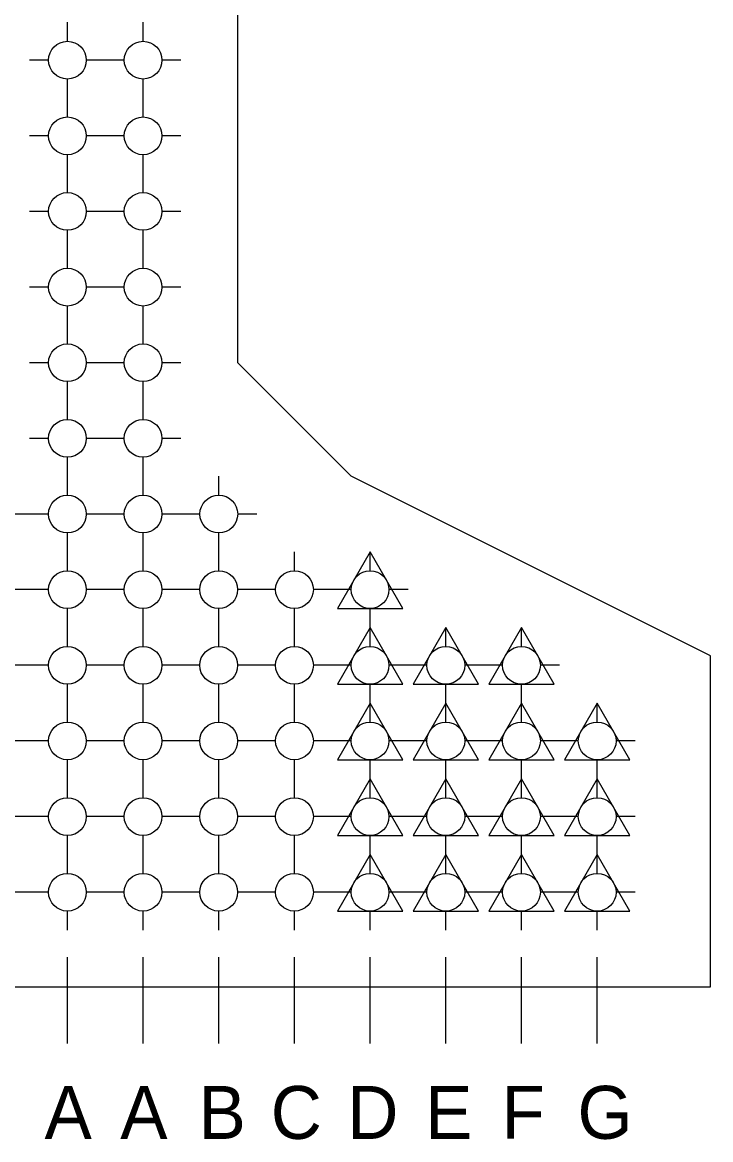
# Model space of a CAD drawing. Extents: x 998.6 to 1033.3, y 1000 to 1011.
# Drawn here: x 1010.397 to 1011.155, y 1001.342 to 1002.573 of the extents above; entities that cross this region are included whole.
import ezdxf

# ---------------------------------------------------------------- set-up
doc = ezdxf.new("R2010")
doc.units = 0
doc.layers.add('Working Level 1', color=7, linetype='Continuous')

msp = doc.modelspace()

# ---------------------------------------------------------------- linework, layer by layer
at = {"layer": 'Working Level 1'}
for p, q in [((1010.6339, 1002.1977), (1010.6339, 1004.0935)), ((1010.4465, 1002.552), (1010.4465, 1002.5729)), ((1010.5298, 1002.552), (1010.5298, 1002.5729)), ((1010.4256, 1002.5312), (1010.4048, 1002.5312)), ((1010.4881, 1002.5312), (1010.4673, 1002.5312)), ((1010.5089, 1002.5312), (1010.4881, 1002.5312)), ((1010.5714, 1002.5312), (1010.5506, 1002.5312)), ((1010.4464, 1002.4895), (1010.4464, 1002.5104)), ((1010.5297, 1002.4895), (1010.5297, 1002.5104)), ((1010.4465, 1002.4687), (1010.4465, 1002.4895)), ((1010.5298, 1002.4687), (1010.5298, 1002.4895)), ((1010.4256, 1002.4478), (1010.4048, 1002.4478)), ((1010.4881, 1002.4478), (1010.4673, 1002.4478)), ((1010.5089, 1002.4478), (1010.4881, 1002.4478)), ((1010.5714, 1002.4478), (1010.5506, 1002.4478)), ((1010.4464, 1002.4062), (1010.4464, 1002.427)), ((1010.5297, 1002.4062), (1010.5297, 1002.427)), ((1010.4465, 1002.3853), (1010.4465, 1002.4062)), ((1010.5298, 1002.3853), (1010.5298, 1002.4062)), ((1010.4256, 1002.3645), (1010.4048, 1002.3645)), ((1010.4881, 1002.3645), (1010.4673, 1002.3645)), ((1010.5089, 1002.3645), (1010.4881, 1002.3645)), ((1010.5714, 1002.3645), (1010.5506, 1002.3645)), ((1010.4464, 1002.3228), (1010.4464, 1002.3437)), ((1010.5297, 1002.3228), (1010.5297, 1002.3437)), ((1010.4465, 1002.302), (1010.4465, 1002.3228)), ((1010.5298, 1002.302), (1010.5298, 1002.3228)), ((1010.4256, 1002.2811), (1010.4048, 1002.2811)), ((1010.4881, 1002.2811), (1010.4673, 1002.2811)), ((1010.5089, 1002.2811), (1010.4881, 1002.2811)), ((1010.5714, 1002.2811), (1010.5506, 1002.2811)), ((1010.4464, 1002.2395), (1010.4464, 1002.2603)), ((1010.5297, 1002.2395), (1010.5297, 1002.2603)), ((1010.4464, 1002.2186), (1010.4464, 1002.2395)), ((1010.5297, 1002.2186), (1010.5297, 1002.2395)), ((1010.4256, 1002.1978), (1010.4047, 1002.1978)), ((1010.4881, 1002.1978), (1010.4672, 1002.1978)), ((1010.5089, 1002.1978), (1010.488, 1002.1978)), ((1010.5714, 1002.1978), (1010.5505, 1002.1978)), ((1010.7589, 1002.0727), (1010.6339, 1002.1977)), ((1010.4464, 1002.1561), (1010.4464, 1002.177)), ((1010.5297, 1002.1561), (1010.5297, 1002.177)), ((1010.4464, 1002.1353), (1010.4464, 1002.1561)), ((1010.5297, 1002.1353), (1010.5297, 1002.1561)), ((1010.4256, 1002.1145), (1010.4047, 1002.1145)), ((1010.4881, 1002.1145), (1010.4672, 1002.1145)), ((1010.5089, 1002.1145), (1010.488, 1002.1145)), ((1010.5714, 1002.1145), (1010.5505, 1002.1145)), ((1010.4464, 1002.0728), (1010.4464, 1002.0936)), ((1010.5297, 1002.0728), (1010.5297, 1002.0936)), ((1010.4464, 1002.0519), (1010.4464, 1002.0728)), ((1010.5297, 1002.0519), (1010.5297, 1002.0728)), ((1010.6131, 1002.0519), (1010.6131, 1002.0728)), ((1011.1547, 1001.8748), (1010.7589, 1002.0727)), ((1010.4048, 1002.0311), (1010.3839, 1002.0311)), ((1010.4256, 1002.0311), (1010.4047, 1002.0311)), ((1010.4881, 1002.0311), (1010.4672, 1002.0311)), ((1010.5089, 1002.0311), (1010.488, 1002.0311)), ((1010.5714, 1002.0311), (1010.5505, 1002.0311)), ((1010.5923, 1002.0311), (1010.5714, 1002.0311)), ((1010.6548, 1002.0311), (1010.6339, 1002.0311)), ((1010.4464, 1001.9894), (1010.4464, 1002.0103)), ((1010.5297, 1001.9894), (1010.5297, 1002.0103)), ((1010.6131, 1001.9894), (1010.6131, 1002.0103)), ((1010.4464, 1001.9686), (1010.4464, 1001.9894)), ((1010.5297, 1001.9686), (1010.5297, 1001.9894)), ((1010.6131, 1001.9686), (1010.6131, 1001.9894)), ((1010.6964, 1001.9686), (1010.6964, 1001.9894)), ((1010.7798, 1001.9894), (1010.7437, 1001.9269)), ((1010.7798, 1001.9686), (1010.7798, 1001.9894)), ((1010.8158, 1001.9269), (1010.7798, 1001.9894)), ((1010.4048, 1001.9478), (1010.3839, 1001.9478)), ((1010.4256, 1001.9478), (1010.4047, 1001.9478)), ((1010.4881, 1001.9478), (1010.4672, 1001.9478)), ((1010.5089, 1001.9478), (1010.488, 1001.9478)), ((1010.5714, 1001.9478), (1010.5505, 1001.9478)), ((1010.5922, 1001.9478), (1010.5714, 1001.9478)), ((1010.6548, 1001.9478), (1010.6339, 1001.9478)), ((1010.6756, 1001.9478), (1010.6547, 1001.9478)), ((1010.7381, 1001.9478), (1010.7172, 1001.9478)), ((1010.7589, 1001.9478), (1010.7381, 1001.9478)), ((1010.8215, 1001.9478), (1010.8006, 1001.9478)), ((1010.4464, 1001.9061), (1010.4464, 1001.9269)), ((1010.5297, 1001.9061), (1010.5297, 1001.9269)), ((1010.613, 1001.9061), (1010.613, 1001.9269)), ((1010.6964, 1001.9061), (1010.6964, 1001.9269)), ((1010.7437, 1001.9269), (1010.8158, 1001.9269)), ((1010.7797, 1001.9061), (1010.7797, 1001.9269)), ((1010.4464, 1001.8852), (1010.4464, 1001.9061)), ((1010.5297, 1001.8852), (1010.5297, 1001.9061)), ((1010.6131, 1001.8852), (1010.6131, 1001.9061)), ((1010.6964, 1001.8852), (1010.6964, 1001.9061)), ((1010.7798, 1001.9061), (1010.7437, 1001.8436)), ((1010.7798, 1001.8852), (1010.7798, 1001.9061)), ((1010.8158, 1001.8436), (1010.7798, 1001.9061)), ((1010.8631, 1001.9061), (1010.827, 1001.8436)), ((1010.8631, 1001.8852), (1010.8631, 1001.9061)), ((1010.8992, 1001.8436), (1010.8631, 1001.9061)), ((1010.9465, 1001.9061), (1010.9104, 1001.8436)), ((1010.9465, 1001.8852), (1010.9465, 1001.9061)), ((1010.9825, 1001.8436), (1010.9465, 1001.9061)), ((1011.1547, 1001.5102), (1011.1547, 1001.8748)), ((1010.4048, 1001.8644), (1010.3839, 1001.8644)), ((1010.4256, 1001.8644), (1010.4047, 1001.8644)), ((1010.4881, 1001.8644), (1010.4672, 1001.8644)), ((1010.5089, 1001.8644), (1010.488, 1001.8644)), ((1010.5714, 1001.8644), (1010.5505, 1001.8644)), ((1010.5922, 1001.8644), (1010.5714, 1001.8644)), ((1010.6548, 1001.8644), (1010.6339, 1001.8644)), ((1010.6756, 1001.8644), (1010.6547, 1001.8644)), ((1010.7381, 1001.8644), (1010.7172, 1001.8644)), ((1010.7589, 1001.8644), (1010.7381, 1001.8644)), ((1010.8215, 1001.8644), (1010.8006, 1001.8644)), ((1010.8423, 1001.8644), (1010.8214, 1001.8644)), ((1010.9048, 1001.8644), (1010.8839, 1001.8644)), ((1010.9256, 1001.8644), (1010.9048, 1001.8644)), ((1010.9882, 1001.8644), (1010.9673, 1001.8644)), ((1010.4464, 1001.8227), (1010.4464, 1001.8436)), ((1010.5297, 1001.8227), (1010.5297, 1001.8436)), ((1010.613, 1001.8227), (1010.613, 1001.8436)), ((1010.6964, 1001.8227), (1010.6964, 1001.8436)), ((1010.7437, 1001.8436), (1010.8158, 1001.8436)), ((1010.7797, 1001.8227), (1010.7797, 1001.8436)), ((1010.827, 1001.8436), (1010.8992, 1001.8436)), ((1010.8631, 1001.8227), (1010.8631, 1001.8436)), ((1010.9104, 1001.8436), (1010.9825, 1001.8436)), ((1010.9464, 1001.8227), (1010.9464, 1001.8436)), ((1010.4464, 1001.8019), (1010.4464, 1001.8227)), ((1010.5297, 1001.8019), (1010.5297, 1001.8227)), ((1010.6131, 1001.8019), (1010.6131, 1001.8227)), ((1010.6964, 1001.8019), (1010.6964, 1001.8227)), ((1010.7798, 1001.8227), (1010.7437, 1001.7602)), ((1010.7798, 1001.8019), (1010.7798, 1001.8227)), ((1010.8158, 1001.7602), (1010.7798, 1001.8227)), ((1010.8631, 1001.8227), (1010.827, 1001.7602)), ((1010.8631, 1001.8019), (1010.8631, 1001.8227)), ((1010.8992, 1001.7602), (1010.8631, 1001.8227)), ((1010.9465, 1001.8227), (1010.9104, 1001.7602)), ((1010.9465, 1001.8019), (1010.9465, 1001.8227)), ((1010.9825, 1001.7602), (1010.9465, 1001.8227)), ((1011.0298, 1001.8227), (1010.9937, 1001.7602)), ((1011.0298, 1001.8019), (1011.0298, 1001.8227)), ((1011.0659, 1001.7602), (1011.0298, 1001.8227)), ((1010.4048, 1001.7811), (1010.3839, 1001.7811)), ((1010.4256, 1001.7811), (1010.4047, 1001.7811)), ((1010.4881, 1001.7811), (1010.4672, 1001.7811)), ((1010.5089, 1001.7811), (1010.488, 1001.7811)), ((1010.5714, 1001.7811), (1010.5505, 1001.7811)), ((1010.5922, 1001.7811), (1010.5714, 1001.7811)), ((1010.6548, 1001.7811), (1010.6339, 1001.7811)), ((1010.6756, 1001.7811), (1010.6547, 1001.7811)), ((1010.7381, 1001.7811), (1010.7172, 1001.7811)), ((1010.7589, 1001.7811), (1010.7381, 1001.7811)), ((1010.8215, 1001.7811), (1010.8006, 1001.7811)), ((1010.8423, 1001.7811), (1010.8214, 1001.7811)), ((1010.9048, 1001.7811), (1010.8839, 1001.7811)), ((1010.9256, 1001.7811), (1010.9048, 1001.7811)), ((1010.9882, 1001.7811), (1010.9673, 1001.7811)), ((1011.009, 1001.7811), (1010.9881, 1001.7811)), ((1011.0715, 1001.7811), (1011.0506, 1001.7811)), ((1010.4464, 1001.7394), (1010.4464, 1001.7602)), ((1010.5297, 1001.7394), (1010.5297, 1001.7602)), ((1010.613, 1001.7394), (1010.613, 1001.7602)), ((1010.6964, 1001.7394), (1010.6964, 1001.7602)), ((1010.7437, 1001.7602), (1010.8158, 1001.7602)), ((1010.7797, 1001.7394), (1010.7797, 1001.7602)), ((1010.827, 1001.7602), (1010.8992, 1001.7602)), ((1010.8631, 1001.7394), (1010.8631, 1001.7602)), ((1010.9104, 1001.7602), (1010.9825, 1001.7602)), ((1010.9464, 1001.7394), (1010.9464, 1001.7602)), ((1010.9937, 1001.7602), (1011.0659, 1001.7602)), ((1011.0298, 1001.7394), (1011.0298, 1001.7602)), ((1010.4464, 1001.7185), (1010.4464, 1001.7394)), ((1010.5297, 1001.7185), (1010.5297, 1001.7394)), ((1010.6131, 1001.7185), (1010.6131, 1001.7394)), ((1010.6964, 1001.7185), (1010.6964, 1001.7394)), ((1010.7798, 1001.7394), (1010.7437, 1001.6769)), ((1010.7798, 1001.7185), (1010.7798, 1001.7394)), ((1010.8158, 1001.6769), (1010.7798, 1001.7394)), ((1010.8631, 1001.7394), (1010.827, 1001.6769)), ((1010.8631, 1001.7185), (1010.8631, 1001.7394)), ((1010.8992, 1001.6769), (1010.8631, 1001.7394)), ((1010.9465, 1001.7394), (1010.9104, 1001.6769)), ((1010.9465, 1001.7185), (1010.9465, 1001.7394)), ((1010.9825, 1001.6769), (1010.9465, 1001.7394)), ((1011.0298, 1001.7394), (1010.9937, 1001.6769)), ((1011.0298, 1001.7185), (1011.0298, 1001.7394)), ((1011.0659, 1001.6769), (1011.0298, 1001.7394)), ((1010.4048, 1001.6977), (1010.3839, 1001.6977)), ((1010.4256, 1001.6977), (1010.4047, 1001.6977)), ((1010.4881, 1001.6977), (1010.4672, 1001.6977)), ((1010.5089, 1001.6977), (1010.488, 1001.6977)), ((1010.5714, 1001.6977), (1010.5505, 1001.6977)), ((1010.5922, 1001.6977), (1010.5714, 1001.6977)), ((1010.6548, 1001.6977), (1010.6339, 1001.6977)), ((1010.6756, 1001.6977), (1010.6547, 1001.6977)), ((1010.7381, 1001.6977), (1010.7172, 1001.6977)), ((1010.7589, 1001.6977), (1010.7381, 1001.6977)), ((1010.8215, 1001.6977), (1010.8006, 1001.6977)), ((1010.8423, 1001.6977), (1010.8214, 1001.6977)), ((1010.9048, 1001.6977), (1010.8839, 1001.6977)), ((1010.9256, 1001.6977), (1010.9048, 1001.6977)), ((1010.9882, 1001.6977), (1010.9673, 1001.6977)), ((1011.009, 1001.6977), (1010.9881, 1001.6977)), ((1011.0715, 1001.6977), (1011.0506, 1001.6977)), ((1010.4464, 1001.656), (1010.4464, 1001.6769)), ((1010.5297, 1001.656), (1010.5297, 1001.6769)), ((1010.613, 1001.656), (1010.613, 1001.6769)), ((1010.6964, 1001.656), (1010.6964, 1001.6769)), ((1010.7437, 1001.6769), (1010.8158, 1001.6769)), ((1010.7797, 1001.656), (1010.7797, 1001.6769)), ((1010.827, 1001.6769), (1010.8992, 1001.6769)), ((1010.8631, 1001.656), (1010.8631, 1001.6769)), ((1010.9104, 1001.6769), (1010.9825, 1001.6769)), ((1010.9464, 1001.656), (1010.9464, 1001.6769)), ((1010.9937, 1001.6769), (1011.0659, 1001.6769)), ((1011.0298, 1001.656), (1011.0298, 1001.6769)), ((1010.4464, 1001.6352), (1010.4464, 1001.656)), ((1010.5297, 1001.6352), (1010.5297, 1001.656)), ((1010.6131, 1001.6352), (1010.6131, 1001.656)), ((1010.6964, 1001.6352), (1010.6964, 1001.656)), ((1010.7798, 1001.656), (1010.7437, 1001.5935)), ((1010.7798, 1001.6352), (1010.7798, 1001.656)), ((1010.8158, 1001.5935), (1010.7798, 1001.656)), ((1010.8631, 1001.656), (1010.827, 1001.5935)), ((1010.8631, 1001.6352), (1010.8631, 1001.656)), ((1010.8992, 1001.5935), (1010.8631, 1001.656)), ((1010.9465, 1001.656), (1010.9104, 1001.5935)), ((1010.9465, 1001.6352), (1010.9465, 1001.656)), ((1010.9825, 1001.5935), (1010.9465, 1001.656)), ((1011.0298, 1001.656), (1010.9937, 1001.5935)), ((1011.0298, 1001.6352), (1011.0298, 1001.656)), ((1011.0659, 1001.5935), (1011.0298, 1001.656)), ((1010.4048, 1001.6144), (1010.3839, 1001.6144)), ((1010.4256, 1001.6144), (1010.4047, 1001.6144)), ((1010.4881, 1001.6144), (1010.4672, 1001.6144)), ((1010.5089, 1001.6144), (1010.488, 1001.6144)), ((1010.5714, 1001.6144), (1010.5505, 1001.6144)), ((1010.5922, 1001.6144), (1010.5714, 1001.6144)), ((1010.6548, 1001.6144), (1010.6339, 1001.6144)), ((1010.6756, 1001.6144), (1010.6547, 1001.6144)), ((1010.7381, 1001.6144), (1010.7172, 1001.6144)), ((1010.7589, 1001.6144), (1010.7381, 1001.6144)), ((1010.8215, 1001.6144), (1010.8006, 1001.6144)), ((1010.8423, 1001.6144), (1010.8214, 1001.6144)), ((1010.9048, 1001.6144), (1010.8839, 1001.6144)), ((1010.9256, 1001.6144), (1010.9048, 1001.6144)), ((1010.9882, 1001.6144), (1010.9673, 1001.6144)), ((1011.009, 1001.6144), (1010.9881, 1001.6144)), ((1011.0715, 1001.6144), (1011.0506, 1001.6144)), ((1010.4464, 1001.5727), (1010.4464, 1001.5935)), ((1010.5297, 1001.5727), (1010.5297, 1001.5935)), ((1010.613, 1001.5727), (1010.613, 1001.5935)), ((1010.6964, 1001.5727), (1010.6964, 1001.5935)), ((1010.7437, 1001.5935), (1010.8158, 1001.5935)), ((1010.7797, 1001.5727), (1010.7797, 1001.5935)), ((1010.827, 1001.5935), (1010.8992, 1001.5935)), ((1010.8631, 1001.5727), (1010.8631, 1001.5935)), ((1010.9104, 1001.5935), (1010.9825, 1001.5935)), ((1010.9464, 1001.5727), (1010.9464, 1001.5935)), ((1010.9937, 1001.5935), (1011.0659, 1001.5935)), ((1011.0298, 1001.5727), (1011.0298, 1001.5935)), ((1010.4464, 1001.4477), (1010.4464, 1001.5427)), ((1010.5297, 1001.4477), (1010.5297, 1001.5427)), ((1010.613, 1001.4477), (1010.613, 1001.5427)), ((1010.6964, 1001.4477), (1010.6964, 1001.5427)), ((1010.7797, 1001.4477), (1010.7797, 1001.5427)), ((1010.8631, 1001.4477), (1010.8631, 1001.5427)), ((1010.9464, 1001.4477), (1010.9464, 1001.5427)), ((1011.0298, 1001.4477), (1011.0298, 1001.5427)), ((1009.8214, 1001.5102), (1011.1547, 1001.5102))]:
    msp.add_line(p, q, dxfattribs=at)
for centre in [(1010.4464, 1002.5312), (1010.5297, 1002.5312), (1010.4464, 1002.4478), (1010.5297, 1002.4478), (1010.4464, 1002.3645), (1010.5297, 1002.3645), (1010.4464, 1002.2811), (1010.5297, 1002.2811), (1010.4464, 1002.1978), (1010.5297, 1002.1978), (1010.4464, 1002.1145), (1010.5297, 1002.1145), (1010.4464, 1002.0311), (1010.5297, 1002.0311), (1010.6131, 1002.0311), (1010.4464, 1001.9478), (1010.5297, 1001.9478), (1010.613, 1001.9478), (1010.6964, 1001.9478), (1010.7797, 1001.9478), (1010.4464, 1001.8644), (1010.5297, 1001.8644), (1010.613, 1001.8644), (1010.6964, 1001.8644), (1010.7797, 1001.8644), (1010.8631, 1001.8644), (1010.9464, 1001.8644), (1010.4464, 1001.7811), (1010.5297, 1001.7811), (1010.613, 1001.7811), (1010.6964, 1001.7811), (1010.7797, 1001.7811), (1010.8631, 1001.7811), (1010.9464, 1001.7811), (1011.0298, 1001.7811), (1010.4464, 1001.6977), (1010.5297, 1001.6977), (1010.613, 1001.6977), (1010.6964, 1001.6977), (1010.7797, 1001.6977), (1010.8631, 1001.6977), (1010.9464, 1001.6977), (1011.0298, 1001.6977), (1010.4464, 1001.6144), (1010.5297, 1001.6144), (1010.613, 1001.6144), (1010.6964, 1001.6144), (1010.7797, 1001.6144), (1010.8631, 1001.6144), (1010.9464, 1001.6144), (1011.0298, 1001.6144)]:
    msp.add_circle(centre, 0.0208, dxfattribs=at)

# ---------------------------------------------------------------- texts
for s, p in [('A', (1010.4212, 1001.3426)), ('A', (1010.5046, 1001.3426)), ('B', (1010.5909, 1001.3426)), ('C', (1010.6703, 1001.3426)), ('D', (1010.7546, 1001.3426)), ('E', (1010.8405, 1001.3426)), ('F', (1010.9244, 1001.3427)), ('G', (1011.0081, 1001.3427))]:
    msp.add_text(s, height=0.0583, dxfattribs=at).set_placement(p)

doc.saveas('drawing.dxf')
